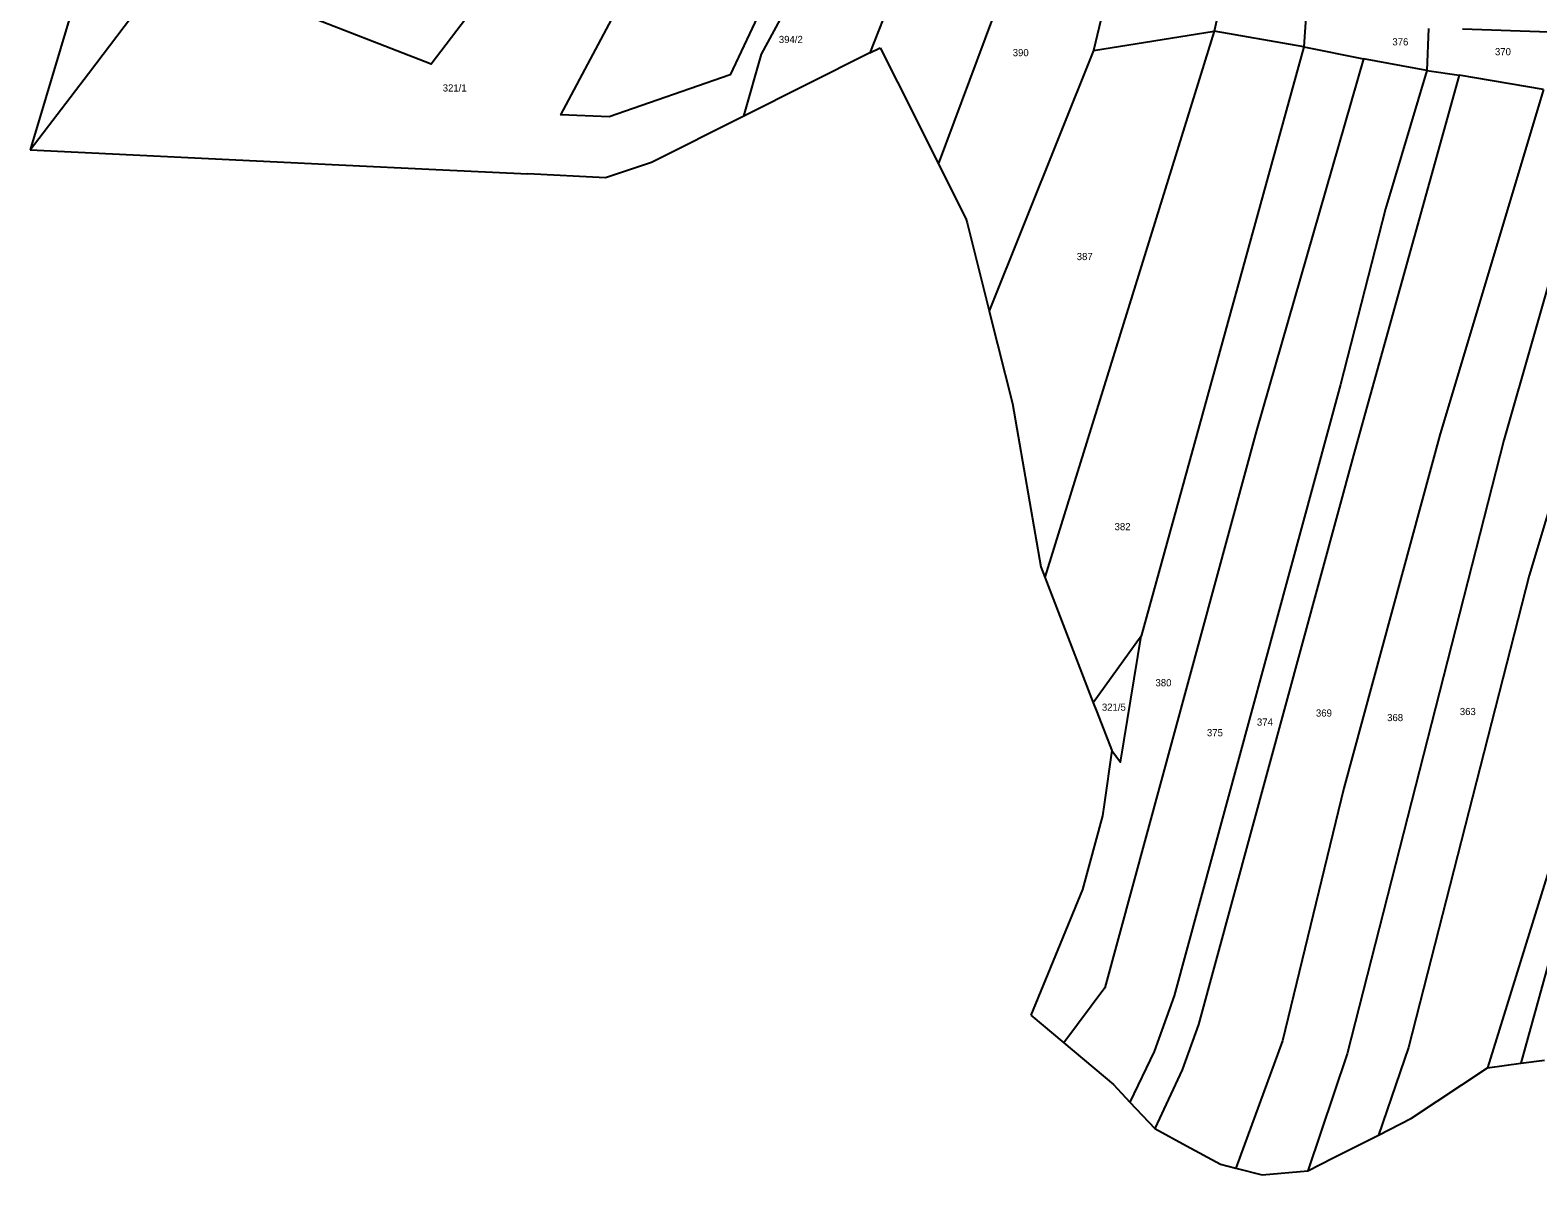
# Model space of a CAD drawing. Extents: x -744566 to -741843, y -1128407 to -1126744.
# Drawn here: x -744013.6 to -743655.8, y -1128009.6 to -1127737.9 of the extents above; entities that cross this region are included whole.
import ezdxf

# ---------------------------------------------------------------- set-up
doc = ezdxf.new("R2010")
doc.units = 0
doc.layers.add('Hranice parcel', color=7, linetype='Continuous')
doc.layers.add('Parcelní čísla', color=7, linetype='Continuous')

msp = doc.modelspace()

# ---------------------------------------------------------------- linework, layer by layer
at = {"layer": 'Hranice parcel'}
for p, q in [((-743799.83, -1127706.36), (-743814.29, -1127743.33)), ((-743798.01, -1127769.73), (-743779.45, -1127719.83)), ((-743756.8, -1127724.26), (-743761.26, -1127742.79)), ((-743730.37, -1127728.24), (-743732.64, -1127738.2)), ((-744002.49, -1127729.2), (-744013.58, -1127766.31)), ((-743710.85, -1127734.84), (-743711.36, -1127741.87)), ((-743732.64, -1127738.2), (-743772.75, -1127867.77)), ((-743761.26, -1127742.79), (-743732.64, -1127738.2)), ((-743711.36, -1127741.87), (-743732.64, -1127738.2)), ((-743681.73, -1127737.55), (-743682.17, -1127747.48)), ((-743653.09, -1127738.43), (-743673.66, -1127737.68)), ((-743814.29, -1127743.33), (-743811.84, -1127742.1)), ((-743811.84, -1127742.1), (-743803.66, -1127758.46)), ((-743761.26, -1127742.79), (-743786, -1127804.52)), ((-743711.36, -1127741.87), (-743749.96, -1127881.78)), ((-743711.36, -1127741.87), (-743697.14, -1127744.72)), ((-743814.29, -1127743.33), (-743844.2, -1127758.32)), ((-743682.17, -1127747.48), (-743697.14, -1127744.72)), ((-743682.17, -1127747.48), (-743674.43, -1127748.6)), ((-743654.42, -1127752.06), (-743674.43, -1127748.6)), ((-743803.66, -1127758.46), (-743798.01, -1127769.73)), ((-744013.58, -1127766.31), (-743940.34, -1127769.88)), ((-743940.34, -1127769.88), (-743917.34, -1127771)), ((-743917.34, -1127771), (-743895.51, -1127772.06)), ((-743798.01, -1127769.73), (-743797.09, -1127771.57)), ((-743791.23, -1127783.7), (-743786, -1127804.52)), ((-743786, -1127804.52), (-743785.74, -1127805.57)), ((-743785.74, -1127805.57), (-743780.48, -1127826.53)), ((-743780.48, -1127826.53), (-743773.7, -1127865.3)), ((-743773.7, -1127865.3), (-743772.75, -1127867.77)), ((-743772.75, -1127867.77), (-743761.28, -1127897.56)), ((-743749.96, -1127881.78), (-743761.28, -1127897.56)), ((-743761.28, -1127897.56), (-743760.44, -1127899.72)), ((-743760.44, -1127899.72), (-743756.9, -1127908.92)), ((-743756.9, -1127908.92), (-743758.74, -1127921.72)), ((-743776.13, -1127971.68), (-743768.26, -1127978.29)), ((-743659.84, -1127983.12), (-743654.23, -1127982.34)), ((-743667.73, -1127984.22), (-743659.84, -1127983.12)), ((-743752.61, -1127992.31), (-743746.7, -1127998.56)), ((-743704.36, -1128005.57), (-743693.63, -1128000.15)), ((-743731.1, -1128007.03), (-743727.47, -1128007.97)), ((-743710.41, -1128008.62), (-743704.36, -1128005.57))]:
    msp.add_line(p, q, dxfattribs=at)
for points in [[(-743863.3, -1127673.64), (-743918.42, -1127746.02), (-743953.89, -1127732.21), (-743893.74, -1127654.46)], [(-743821.37, -1127693.07), (-743847.43, -1127748.51), (-743876.2, -1127758.54), (-743887.66, -1127758.02), (-743848.02, -1127683.56)], [(-744013.58, -1127766.31), (-743999.71, -1127748.24), (-743959.16, -1127694.66)], [(-743844.2, -1127758.32), (-743840, -1127743.62), (-743813.91, -1127695.5)], [(-743697.14, -1127744.72), (-743722.54, -1127832.92), (-743758.56, -1127965.24), (-743768.26, -1127978.29)], [(-743682.17, -1127747.48), (-743691.92, -1127780.31), (-743702.59, -1127822), (-743742.13, -1127967.1), (-743746.82, -1127980.32), (-743752.61, -1127992.31)], [(-743674.43, -1127748.6), (-743699.34, -1127837.9), (-743736.36, -1127973.94), (-743740.21, -1127984.65), (-743746.7, -1127998.56)], [(-743654.42, -1127752.06), (-743678.95, -1127833.74), (-743701.86, -1127917.81), (-743716.39, -1127977.76), (-743727.47, -1128007.97)], [(-743638.13, -1127755.73), (-743649.76, -1127786.02), (-743663.84, -1127835.21), (-743701.08, -1127980.88), (-743710.41, -1128008.62)], [(-743844.2, -1127758.32), (-743866.16, -1127769.33), (-743877.07, -1127772.96), (-743895.51, -1127772.06)], [(-743623.67, -1127759.6), (-743635.09, -1127791.61), (-743657.85, -1127867.39), (-743686.5, -1127979.4), (-743693.63, -1128000.15)], [(-743603.54, -1127766.74), (-743612.96, -1127791.11), (-743627.05, -1127838.6), (-743649.69, -1127926.04), (-743667.73, -1127984.22)], [(-743597.33, -1127768.16), (-743606.36, -1127789.97), (-743626.72, -1127859.49), (-743638.35, -1127905.26), (-743659.84, -1127983.12)], [(-743797.09, -1127771.57), (-743791.43, -1127782.89), (-743791.23, -1127783.7)], [(-743756.9, -1127908.92), (-743754.87, -1127911.67), (-743749.96, -1127881.78)], [(-743758.74, -1127921.72), (-743759.13, -1127924.43), (-743763.85, -1127941.89), (-743776.13, -1127971.68)], [(-743768.26, -1127978.29), (-743756.53, -1127988.15), (-743752.61, -1127992.31)], [(-743693.63, -1128000.15), (-743685.74, -1127996.16), (-743667.73, -1127984.22)], [(-743746.7, -1127998.56), (-743739.19, -1128002.73), (-743731.1, -1128007.03)], [(-743727.47, -1128007.97), (-743721.18, -1128009.59), (-743710.41, -1128008.62)]]:
    msp.add_lwpolyline(points, dxfattribs=at)

# ---------------------------------------------------------------- texts
at = {"layer": 'Parcelní čísla'}
for s, p in [('394/2', (-743835.91, -1127741)), ('390', (-743780.41, -1127744.12)), ('376', (-743690.32, -1127741.56)), ('370', (-743665.97, -1127743.9)), ('321/1', (-743915.68, -1127752.5)), ('387', (-743765.22, -1127792.51)), ('382', (-743756.24, -1127856.61)), ('380', (-743746.53, -1127893.65)), ('321/5', (-743759.25, -1127899.45)), ('369', (-743708.45, -1127900.84)), ('368', (-743691.56, -1127901.92)), ('363', (-743674.31, -1127900.48)), ('375', (-743734.32, -1127905.51)), ('374', (-743722.46, -1127902.99))]:
    msp.add_text(s, height=1.7, dxfattribs=at).set_placement(p)

doc.saveas('drawing.dxf')
